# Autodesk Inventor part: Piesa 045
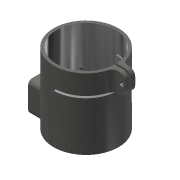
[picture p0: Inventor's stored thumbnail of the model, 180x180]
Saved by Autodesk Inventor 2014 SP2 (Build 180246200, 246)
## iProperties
Created: 2009-01
Part Number: Piesa 045
Document SubType Name: Modeling
Designer: Costel
Material: Steel, Cast
Density: 7.85 g/cm^3
Appearance: Steel - Cast
Author: Costel
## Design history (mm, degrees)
sketch "Sketch1"
  geometry: L1 (-39.6, 0)-(52.8, 0) reference; L2 (0, -39.6)-(0, 52.8) reference; C1 r 33 at (0, 0)
  constraints: 2 point on line, 1 centre point
  dimensions: "d0" = 66 diameter of C1
extrude "Extrusion1" new body sketch "Sketch1" distance "d1" = 72; taper "d2" = 0 deg
hole "Hole1" diameter "d5" = 60; stored, may be unused: countersink angle "d9" = 90 deg, drill point angle "d11" = 118 deg; dims "d3" = 10, "d4" = 10, "d6" = 6, "d7" = 4, "d8" = 2, "d10" = 8
sketch "Sketch2"
  geometry: L1 (0, -39.6)-(0, 52.8) reference; L2 (-39.6, 0)-(52.8, 0) reference; L3 (32.619, 5)-(45, 5); L4 (45, 5)-(45, -5); L5 (32.619, -5)-(45, -5); C1 r 30 at (0, 0) reference; A1 r 33 centre (0, 0) between (32.619, -5) and (32.619, 5); 1 further point
  constraints: 6 end point, 2 point on circle, 2 symmetric about line, 1 centre point, 1 concentric, 1 midpoint, 1 parallel, 1 perpendicular, 1 point on line
  dimensions: "d12" = 10 distance of L3.end L4.end; "d13" = 45 distance between parallel lines of L1 L4; "d15" = 33 radius of A1 (= 0.5 x d0)
extrude "Extrusion2" join sketch "Sketch2" distance "d16" = 20; taper "d17" = 0 deg
sketch "Sketch3"
  geometry: L1 (45, 5)-(45, -5) reference; L2 (0, 1)-(45, 1); L3 (45, 1)-(45, -1); L4 (45, -1)-(0, -1); L5 (0, -1)-(0, 1); L6 (-40.8, 0)-(68.4, 0) reference; C1 r 30 at (0, 0) reference
  constraints: 8 end point, 2 parallel, 1 collinear, 1 horizontal, 1 midpoint, 1 perpendicular, 1 other
  dimensions: "d18" = 2 distance between parallel lines of L4 L2
extrude "Extrusion3" cut sketch "Sketch3" distance "d19" = 20; taper "d20" = 0 deg
sketch "Sketch4"
  geometry: L1 (20, 0)-(20, 4) reference; L2 (20, 38)-(22, 38); L3 (22, 38)-(22, -28); L4 (22, -28)-(20, -28); L5 (20, -28)-(20, 38); L6 (79.2, 5)-(-21.6, 5) reference; L7 (72, 38)-(0, 38) reference; L8 (72, -28)-(0, -28) reference
  constraints: 8 end point, 3 collinear, 2 parallel, 1 horizontal, 1 perpendicular
  dimensions: "d21" = 2 distance of L2.start L2.end
extrude "Extrusion4" cut sketch "Sketch4" distance "d22" = 45 (= d13); taper "d23" = 0 deg
fillet "Fillet1" dims "d24" = 6
hole "Hole2" diameter "d27" = 4; stored, may be unused: countersink angle "d31" = 90 deg, drill point angle "d33" = 118 deg; dims "d25" = 10 (= 0.5 x d16), "d26" = 4 (computed from d13), "d28" = 6, "d29" = 4, "d30" = 2, "d32" = 8
workplane "Work Plane1"
sketch "Sketch5"
  geometry: L1 (0, -7.2)-(0, 93.6) reference; L2 (18, 35)-(-18, 35); L3 (-22, 31)-(-22, 9); L4 (-18, 5)-(18, 5); L5 (22, 9)-(22, 31); L6 (-33, 0)-(33, 0) reference; A1 r 4 centre (18, 31) between (22, 31) and (18, 35); A2 r 4 centre (-18, 31) between (-18, 35) and (-22, 31); A3 r 4 centre (18, 9) between (18, 5) and (22, 9); A4 r 4 centre (-18, 9) between (-22, 9) and (-18, 5); 3 further points
  constraints: 8 end point, 8 point on circle, 8 tangent, 6 point on line, 4 centre point, 3 equal radius, 2 parallel, 1 horizontal, 1 perpendicular, 1 other
  dimensions: "d35" = 30 distance of point (22, 5) point (22, 35); "d36" = 5 distance between parallel lines of L6 L4 (computed from d35); "d37" = 44 distance of point (22, 35) point (-22, 35); "d38" = 4 radius of A1
extrude "Extrusion5" join sketch "Sketch5" stored distance "d39" = 45 (= d13); taper "d40" = 0 deg
sketch "Sketch6"
  geometry: A1 r 4 centre (18, 31) between (22, 31) and (18, 35) reference; A2 r 4 centre (-18, 31) between (-18, 35) and (-22, 31) reference; A3 r 4 centre (-18, 9) between (-22, 9) and (-18, 5) reference; A4 r 4 centre (18, 9) between (18, 5) and (22, 9) reference; 4 further points
  constraints: 4 coincident
hole "Hole3" sketch "Sketch6" at (18, 31), (-18, 31), (-18, 9), (18, 9) diameter "d41" = 3.242; stored, may be unused: countersink angle "d45" = 90 deg, drill point angle "d47" = 118 deg; dims "d42" = 6, "d43" = 4, "d44" = 2, "d46" = 8
sketch "Sketch7"
  geometry: L1 (0, -7.2)-(0, 93.6) reference; L2 (25.674, 20)-(-25.674, 20); L3 (-18, 35)-(18, 35) reference; L4 (18, 5)-(-18, 5) reference; L5 (-39.6, 0)-(52.8, 0) reference; 1 further point
  constraints: 2 end point, 1 midpoint, 1 perpendicular, 1 point on line
  dimensions: "d48" = 20 distance between parallel lines of L5 L2
hole "Hole4" sketch "Sketch7" at (0, 20) diameter "d49" = 21; stored, may be unused: countersink angle "d53" = 90 deg, drill point angle "d55" = 118 deg; dims "d50" = 6, "d51" = 4, "d52" = 2, "d54" = 8
chamfer "Chamfer1" distance "d56" = 0.5; stored, may be unused: second distance "d57" = 2, angle "d58" = 45 deg
fillet "Fillet2" dims "d59" = 6
fillet "Fillet3" dims "d60" = 2
fillet "Fillet4" dims "d61" = 2
body "Solid1"
other parameters: "d34" = -37
